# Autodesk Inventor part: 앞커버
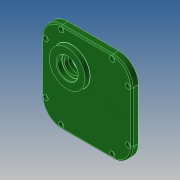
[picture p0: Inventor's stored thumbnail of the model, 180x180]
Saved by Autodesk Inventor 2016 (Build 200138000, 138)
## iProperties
Created: 2016-12
Part Number: 앞커버
Material: 알루미늄 6061
Document SubType Name: Modeling
Designer: mduedu
Density: 2.71 g/cm^3
Mass: 518.945 g
Surface Area: 476.271 cm^2
Volume: 191.493 cm^3
Appearance: 매끄러움 - 짙은 산림 녹색
Author: mduedu
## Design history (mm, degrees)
sketch "스케치1"
  geometry: L1 (-46, 42)-(-46, -36); L2 (-16, 72)-(62, 72); L3 (92, 42)-(92, -36); L4 (62, -66)-(-16, -66); A1 r 30 centre (-16, -36) between (-46, -36) and (-16, -66); A2 r 30 centre (62, 42) between (92, 42) and (62, 72); A3 r 30 centre (62, -36) between (62, -66) and (92, -36); A4 r 30 centre (-16, 42) between (-16, 72) and (-46, 42); 1 further point
  constraints: 8 end point, 8 point on circle, 8 tangent, 4 centre point, 3 equal radius, 2 perpendicular, 1 horizontal
  dimensions: "d89" = 30 radius of A2; "d90" = 92 distance from line of L3 point (0, 0); "d91" = 138 distance between parallel lines of L4 L2; "d92" = 72 distance from line of point (0, 0) L2; "d114" = 46 distance from line of point (0, 0) L1
extrude "돌출1" new body sketch "스케치1" distance "d3" = 10; taper "d4" = 0 deg
sketch "스케치2"
  geometry: C1 r 21 at (0, 26); 1 further point
  constraints: 1 centre point, 1 vertical alignment
  dimensions: "d5" = 42 diameter of C1; "d7" = 26 distance of C1.centre point (0, 0)
extrude "돌출2" join sketch "스케치2" distance "d8" = 7; taper "d9" = 0 deg
sketch "스케치3"
  geometry: C1 r 15 at (0, -28.87); C2 r 21 at (0, 26) reference; C3 r 15 at (-54.87, 26); 1 further point
  constraints: 2 centre point, 1 horizontal alignment, 1 vertical alignment
  dimensions: "d10" = 30 diameter of C1; "d71" = 54.87 distance of C1.centre C2.centre; "d94" = 30 diameter of C3; "d95" = 54.87 distance of C2.centre C3.centre
extrude "돌출3" join sketch "스케치3" distance "d12" = 7; taper "d13" = 0 deg; dims "d50" = 90 deg
sketch "스케치4"
  geometry: C1 r 21 at (0, 26) reference; C2 r 28 at (0, 26); 1 further point
  constraints: 1 centre point, 1 coincident
  dimensions: "d14" = 56 diameter of C2
extrude "돌출4" join sketch "스케치4" distance "d15" = 7; taper "d16" = -5 deg
hole "구멍1" diameter "d19" = 35; stored, may be unused: countersink angle "d23" = 90 deg, drill point angle "d25" = 0 deg; dims "d17" = 10, "d18" = 10, "d20" = 6, "d21" = 4, "d22" = 2, "d24" = 10
hole "구멍2" diameter "d28" = 22; stored, may be unused: countersink angle "d32" = 90 deg, drill point angle "d34" = 0 deg; dims "d26" = 10, "d27" = 10, "d29" = 6, "d30" = 4, "d31" = 2, "d33" = 7
hole "구멍8" diameter "d98" = 22; stored, may be unused: countersink angle "d102" = 90 deg, drill point angle "d104" = 0 deg; dims "d96" = 10, "d97" = 10, "d99" = 6, "d100" = 4, "d101" = 2, "d103" = 7
hole "구멍3" diameter "d37" = 19; stored, may be unused: countersink angle "d41" = 90 deg, drill point angle "d43" = 0 deg; dims "d35" = 10, "d36" = 10, "d38" = 6, "d39" = 4, "d40" = 2, "d42" = 1
hole "구멍9" diameter "d107" = 19; stored, may be unused: countersink angle "d111" = 90 deg, drill point angle "d113" = 0 deg; dims "d105" = 10, "d106" = 10, "d108" = 6, "d109" = 4, "d110" = 2, "d112" = 1
hole "구멍4" diameter "d46" = 32; stored, may be unused: countersink angle "d50" = 90 deg, drill point angle "d52" = 0 deg; dims "d44" = 10, "d45" = 10, "d47" = 6, "d48" = 4, "d49" = 2, "d51" = 8
hole "구멍5" diameter "d55" = 25; stored, may be unused: countersink angle "d59" = 90 deg, drill point angle "d61" = 0 deg; dims "d53" = 10, "d54" = 10, "d56" = 6, "d57" = 4, "d58" = 2, "d60" = 8
fillet "모깎기1" dims "d62" = 0.3
fillet "모깎기2" dims "d63" = 2
chamfer "모따기1" distance "d64" = 1; stored, may be unused: second distance "d65" = 2, angle "d66" = 45 deg
fillet "모깎기4" dims "d68" = 2
fillet "모깎기5" dims "d69" = 0.3
fillet "모깎기6" dims "d70" = 2
sketch "스케치5"
  geometry: L1 (62, 72)-(-16, 72) reference; L2 (92, -36)-(92, 42) reference; L3 (-16, -66)-(62, -66) reference; L4 (-46, 42)-(-46, -36) reference; L5 (-40, 42)-(-40, -36); L6 (-16, -60)-(62, -60); L7 (86, -36)-(86, 42); L8 (62, 66)-(-16, 66); A1 r 30 centre (62, 42) between (92, 42) and (62, 72) reference; A2 r 30 centre (62, -36) between (62, -66) and (92, -36) reference; A3 r 30 centre (-16, -36) between (-46, -36) and (-16, -66) reference; A4 r 30 centre (-16, 42) between (-16, 72) and (-46, 42) reference; A5 r 24 centre (-16, -36) between (-40, -36) and (-16, -60); A6 r 24 centre (62, -36) between (62, -60) and (86, -36); A7 r 24 centre (62, 42) between (86, 42) and (62, 66); A8 r 24 centre (-16, 42) between (-16, 66) and (-40, 42)
  constraints: 8 end point, 8 point on circle, 4 centre point, 7 other
  dimensions: "d93" = 6 distance between parallel lines of L5 L4
sketch "스케치7"
  geometry: L1 (62, 66)-(-16, 66) reference; L2 (86, -36)-(86, 42) reference; L3 (-16, -60)-(62, -60) reference; L4 (-40, 42)-(-40, -36) reference; A1 r 24 centre (62, 42) between (86, 42) and (62, 66) reference; A2 r 24 centre (62, -36) between (62, -60) and (86, -36) reference; A3 r 24 centre (-16, -36) between (-40, -36) and (-16, -60) reference; A4 r 24 centre (-16, 42) between (-16, 66) and (-40, 42) reference; 8 further points
  constraints: 8 coincident
hole "구멍7" sketch "스케치7" at (-40, 42), (-40, -36), (-16, -60), (62, -60), (86, -36), (86, 42), (62, 66), (-16, 66) diameter "d80" = 4.5; stored, may be unused: countersink angle "d84" = 90 deg, drill point angle "d86" = 0 deg; dims "d81" = 6, "d82" = 8, "d83" = 4.6, "d85" = 8
node "솔리드1"
